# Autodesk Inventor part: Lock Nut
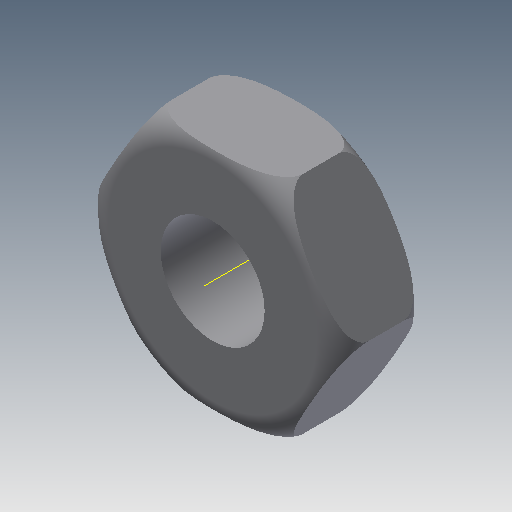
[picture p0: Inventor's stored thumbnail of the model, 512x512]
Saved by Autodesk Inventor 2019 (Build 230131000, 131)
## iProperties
Created: 2009-04
Part Number: Lock Nut
Document SubType Name: Modeling
Designer: Sham
Density: 1 g/cm^3
Material: Generic
Appearance: Default
Author: Sham
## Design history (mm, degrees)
sketch "Sketch1"
  geometry: L1 (7.5, 12.99)-(15, 0); L2 (15, 0)-(7.5, -12.99); L3 (7.5, -12.99)-(-7.5, -12.99); L4 (-7.5, -12.99)-(-15, 0); L5 (-15, 0)-(-7.5, 12.99); L6 (-7.5, 12.99)-(7.5, 12.99); C1 r 6 at (0, 0); 1 further point
  constraints: 12 end point, 1 centre point, 1 coincident, 13 other
  dimensions: "d0" = 30 distance of L1.end L4.end; "d1" = 12 diameter of C1
extrude "Extrusion1" new body sketch "Sketch1" distance "d2" = 10; taper "d3" = 0 deg
sketch "Sketch2"
  geometry: L1 (-12, 0)-(-12, -0.022); L2 (-15, 7)-(-15, 3); L3 (0, -2.87)-(0, 12.87) reference; A1 r 3 centre (-12, 7) between (-12, 10) and (-15, 7); A2 r 3 centre (-12, 3) between (-15, 3) and (-12, 0)
  constraints: 4 end point, 4 point on circle, 2 centre point, 1 tangent
revolve "Revolution1" sketch "Sketch2" stored, may be unused: angle "d7" = 90 deg
body "Solid1"
other parameters: "d6" = 90 deg
